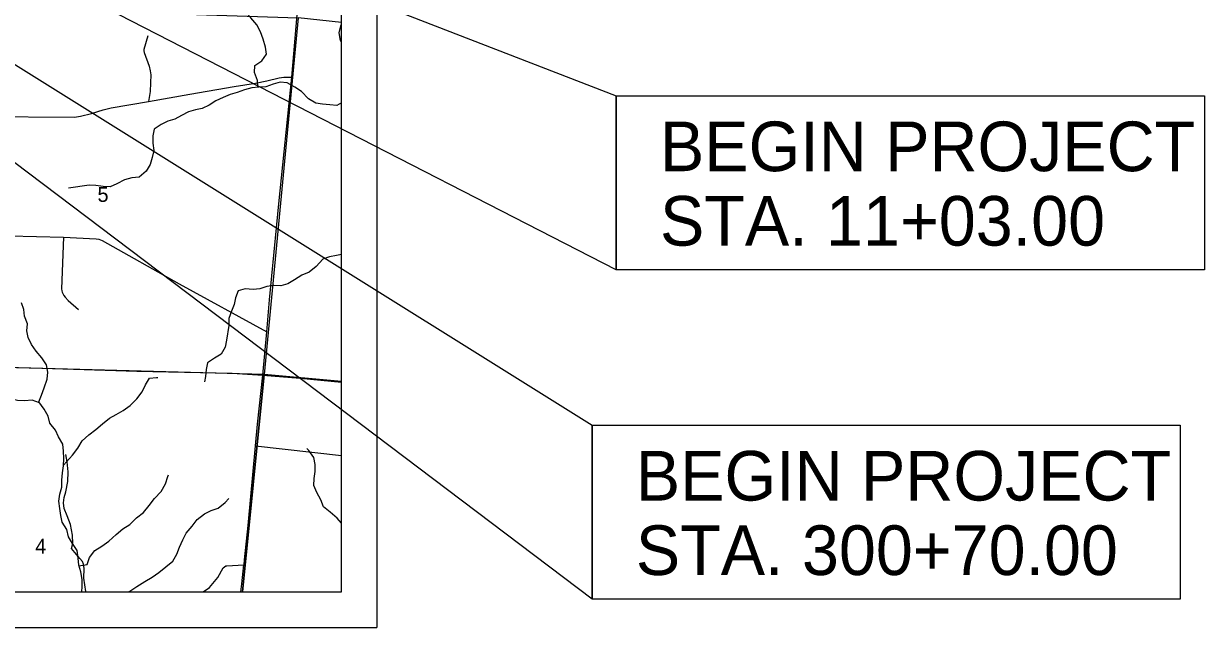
# Model space of a CAD drawing. Extents: x 0 to 34, y -3.9 to 26.2.
# Drawn here: x 8.005 to 11.332, y 14 to 15.703 of the extents above; entities that cross this region are included whole.
import ezdxf

# ---------------------------------------------------------------- set-up
doc = ezdxf.new("R2010")
doc.units = 0
for name, color, linetype in [('GM_X_City_Street', 7, 'Continuous'), ('GM_X_Interchange_Ramps', 7, 'Continuous'), ('GM_X_Interstate_Route', 7, 'Continuous'), ('GM_X_Minor_River', 7, 'Continuous'), ('GM_X_Section', 7, 'Continuous'), ('GM_X_Section_Text', 7, 'Continuous'), ('GM_X_State_Shield', 7, 'Continuous'), ('SH_Data', 7, 'Continuous'), ('SH_Text', 7, 'Continuous')]:
    doc.layers.add(name, color=color, linetype=linetype)

msp = doc.modelspace()

# ---------------------------------------------------------------- linework, layer by layer
at = {"layer": 'GM_X_City_Street'}
msp.add_line((8.6583, 14.512), (8.9, 14.4851), dxfattribs=at)
for points in [[(8.617, 14.1), (8.6198, 14.1232), (8.6255, 14.1764), (8.6256, 14.1778), (8.627, 14.1907), (8.6376, 14.2877), (8.6583, 14.512), (8.664, 14.573), (8.6788, 14.7113), (8.6895, 14.8334), (8.6975, 14.9238), (8.7234, 15.1949), (8.7607, 15.5523), (8.7755, 15.7284), (8.7818, 15.7929), (8.8003, 15.9821), (8.8096, 16.1005)], [(8.3546, 15.6685), (8.3434, 15.6304), (8.3432, 15.6283), (8.3433, 15.6263), (8.3446, 15.6221), (8.358, 15.5833), (8.3609, 15.5698), (8.3627, 15.5588), (8.3624, 15.536), (8.361, 15.5118), (8.356, 15.4837)], [(7.887, 15.4412), (8.1481, 15.4396), (8.1652, 15.4422), (8.1958, 15.4494), (8.2287, 15.4599), (8.2516, 15.4654), (8.356, 15.4837), (8.4725, 15.504), (8.5983, 15.5254), (8.6578, 15.5349), (8.6898, 15.5416), (8.7246, 15.5506), (8.738, 15.5525), (8.7607, 15.5523)], [(7.9645, 15.1041), (8.1174, 15.1004), (8.2093, 15.0964), (8.2169, 15.095), (8.2209, 15.0935), (8.2262, 15.0911), (8.4427, 14.9693), (8.6895, 14.8334)], [(8.1174, 15.1004), (8.1116, 14.9553), (8.1122, 14.9494), (8.1132, 14.9455), (8.1146, 14.9423), (8.1178, 14.9365), (8.1212, 14.9319), (8.1304, 14.9218), (8.1594, 14.897)], [(7.8755, 14.7356), (8.0556, 14.7316), (8.3232, 14.723), (8.592, 14.7171), (8.6788, 14.7113), (8.784, 14.7033), (8.9, 14.6919)], [(8.1801, 14.1), (8.1798, 14.1011), (8.174, 14.1385), (8.1751, 14.1658), (8.1732, 14.1788), (8.1704, 14.1861), (8.163, 14.1943), (8.1395, 14.223), (8.1429, 14.2366), (8.142, 14.2606), (8.1368, 14.2904), (8.1272, 14.3146), (8.119, 14.3354), (8.1171, 14.3514), (8.1187, 14.3666), (8.1237, 14.382), (8.1287, 14.4119), (8.1302, 14.4393), (8.1271, 14.4671), (8.1231, 14.4881)], [(8.5106, 14.1), (8.528, 14.1127), (8.5519, 14.141), (8.5671, 14.1676), (8.571, 14.1713), (8.5741, 14.1733), (8.5772, 14.1741), (8.6255, 14.1764)]]:
    msp.add_lwpolyline(points, dxfattribs=at)
at = {"layer": 'GM_X_Interchange_Ramps'}
msp.add_lwpolyline([(7.395, 14.1), (8.9, 14.1), (8.9, 20.3498)], dxfattribs=at)
at = {"layer": 'GM_X_Interstate_Route'}
msp.add_lwpolyline([(2.5468, 14.1), (8.9, 14.1), (8.9, 16.7226), (8.8708, 16.7253), (8.3218, 16.7826), (8.2541, 16.7887), (8.1936, 16.7941), (8.1769, 16.7957), (7.8848, 16.8273)], dxfattribs=at)
at = {"layer": 'GM_X_Minor_River'}
for points in [[(8.665, 15.5234), (8.6632, 15.543), (8.6552, 15.565), (8.6563, 15.5848), (8.6758, 15.5981), (8.6891, 15.6171), (8.6861, 15.6365), (8.68, 15.6594), (8.6716, 15.6799), (8.6613, 15.7001), (8.6449, 15.7199), (8.6274, 15.7393), (8.6171, 15.7587), (8.5961, 15.7781), (8.5946, 15.7994), (8.5988, 15.8184), (8.6041, 15.8393), (8.6087, 15.861), (8.6113, 15.877)], [(8.9, 15.6502), (8.8976, 15.6556), (8.8941, 15.6769), (8.8983, 15.697), (8.9, 15.7)], [(8.9, 15.4796), (8.8869, 15.4726), (8.8675, 15.4745), (8.8469, 15.4756), (8.8278, 15.479), (8.8076, 15.4912), (8.7874, 15.5114), (8.7684, 15.5236), (8.747, 15.5357), (8.7276, 15.538), (8.7078, 15.5327), (8.6868, 15.5247), (8.6674, 15.5236), (8.648, 15.522), (8.6274, 15.5163), (8.606, 15.5091), (8.5862, 15.503), (8.5668, 15.495), (8.5466, 15.4851), (8.5271, 15.4733), (8.5081, 15.4635), (8.4886, 15.4596), (8.4692, 15.4547), (8.4494, 15.444), (8.4303, 15.4338), (8.4113, 15.4277), (8.3918, 15.4182), (8.3724, 15.4056), (8.3686, 15.3866), (8.369, 15.3661), (8.3713, 15.3448), (8.3671, 15.3257), (8.361, 15.3056), (8.3499, 15.2865), (8.3297, 15.2702), (8.3091, 15.2683), (8.2886, 15.2622), (8.2676, 15.2508), (8.2482, 15.2428), (8.2283, 15.2439), (8.2082, 15.2466), (8.1891, 15.247), (8.1697, 15.2447), (8.1506, 15.242), (8.1308, 15.2394)], [(8.9, 15.0517), (8.8858, 15.0495), (8.8663, 15.0449), (8.8473, 15.0385), (8.8286, 15.0179), (8.8088, 15.0019), (8.7882, 14.9932), (8.7676, 14.9802), (8.7486, 14.9696), (8.7291, 14.9635), (8.7097, 14.9643), (8.6895, 14.9616), (8.6704, 14.9555), (8.651, 14.9536), (8.6289, 14.9551), (8.6091, 14.9494), (8.6018, 14.93), (8.5976, 14.9106), (8.59, 14.8916), (8.5828, 14.8718), (8.5824, 14.8513), (8.5763, 14.8102), (8.5725, 14.7904), (8.5614, 14.7706), (8.5424, 14.7599), (8.5229, 14.7466), (8.5191, 14.7276), (8.5168, 14.7078), (8.5138, 14.693)], [(8.1683, 14.1), (8.1692, 14.1157), (8.1692, 14.1348), (8.1658, 14.1565), (8.1597, 14.1759), (8.1578, 14.1956), (8.1551, 14.2166), (8.1422, 14.2367), (8.1307, 14.2558), (8.1262, 14.2759), (8.1136, 14.2969), (8.1094, 14.3159), (8.1067, 14.3357), (8.1041, 14.3562), (8.1064, 14.376), (8.1121, 14.3958), (8.1125, 14.4156), (8.1144, 14.4358), (8.1167, 14.4555), (8.1178, 14.4765), (8.117, 14.4974), (8.1148, 14.5168), (8.1033, 14.5374), (8.0946, 14.5564), (8.0782, 14.5762), (8.0736, 14.5963), (8.0625, 14.6154), (8.0477, 14.6359), (8.0545, 14.6553), (8.0629, 14.6762), (8.0709, 14.6998), (8.0728, 14.7196), (8.0687, 14.7409), (8.0557, 14.76), (8.0397, 14.7794), (8.0271, 14.7984), (8.0172, 14.8178), (8.0138, 14.8368), (8.0153, 14.8562), (8.0073, 14.8775), (8.005, 14.8966), (7.9985, 14.9156)], [(8.1167, 14.4572), (8.1258, 14.4666), (8.1422, 14.486), (8.1571, 14.5054), (8.1696, 14.5259), (8.1887, 14.5431), (8.2078, 14.5583), (8.2272, 14.5746), (8.2462, 14.5906), (8.2657, 14.6009), (8.2855, 14.6119), (8.3046, 14.626), (8.3236, 14.645), (8.3389, 14.6648), (8.3484, 14.6838), (8.3591, 14.7029), (8.3789, 14.7048), (8.3831, 14.7048)], [(8.0494, 14.6336), (8.029, 14.6409), (8.0073, 14.6393), (7.9871, 14.6401), (7.9673, 14.6447), (7.9471, 14.6481), (7.9276, 14.6447), (7.9074, 14.6355), (7.8876, 14.6237), (7.8689, 14.6043), (7.8476, 14.591), (7.827, 14.5895), (7.8072, 14.5887), (7.7881, 14.5925), (7.7721, 14.6127), (7.7569, 14.6321), (7.7375, 14.6409), (7.7146, 14.6405), (7.7009, 14.6359)], [(8.9, 14.2943), (8.8877, 14.3079), (8.8686, 14.3254), (8.8492, 14.3399), (8.8419, 14.3596), (8.8309, 14.3806), (8.8225, 14.4007), (8.8236, 14.4205), (8.8259, 14.4399), (8.8263, 14.4597), (8.8221, 14.4791), (8.808, 14.4989), (8.8023, 14.5046)], [(8.1605, 14.1733), (8.1837, 14.177), (8.1906, 14.1968), (8.2051, 14.217), (8.2249, 14.2288), (8.2443, 14.2436), (8.2653, 14.2619), (8.2843, 14.2782), (8.3034, 14.2904), (8.3228, 14.3087), (8.3423, 14.3243), (8.3587, 14.344), (8.3731, 14.3638), (8.3918, 14.3832), (8.4048, 14.4049), (8.4105, 14.4255), (8.4124, 14.4308)], [(8.2999, 14.1), (8.3038, 14.1024), (8.3236, 14.1157), (8.3457, 14.1294), (8.3667, 14.1416), (8.3857, 14.1549), (8.4052, 14.1709), (8.4254, 14.1869), (8.436, 14.2067), (8.4436, 14.2261), (8.4536, 14.2466), (8.4627, 14.2657), (8.4791, 14.2854), (8.4936, 14.3045), (8.5142, 14.3208), (8.5332, 14.33), (8.5523, 14.3361), (8.5725, 14.3528), (8.5824, 14.3635)]]:
    msp.add_lwpolyline(points, dxfattribs=at)
at = {"layer": 'GM_X_Section'}
msp.add_lwpolyline([(8.7783, 15.7191), (8.6823, 14.7132), (7.6773, 14.7406), (7.7738, 15.7526)], close=True, dxfattribs=at)
at = {"layer": 'GM_X_State_Shield'}
for points in [[(8.9, 14.6934), (8.9, 15.7064), (8.7783, 15.7191), (8.6823, 14.7132)], [(7.6139, 14.1), (8.6213, 14.1), (8.6823, 14.7132), (7.6773, 14.7406)], [(8.6213, 14.1), (8.9, 14.1), (8.9, 14.6934), (8.6823, 14.7132)]]:
    msp.add_lwpolyline(points, close=True, dxfattribs=at)
at = {"layer": 'SH_Data'}
for p in [(9, 21), (2, 14)]:
    msp.add_line(p, (9, 14), dxfattribs=at)
at = {"layer": 'SH_Text'}
for points in [[(9.6746, 15.4992), (9.6746, 15.0088), (5.7921, 17.0032)], [(9.6066, 14.5701), (9.6066, 14.0797), (5.8602, 16.9149)], [(9.6746, 15.4992), (11.3317, 15.4992), (11.3317, 15.0088), (9.6746, 15.0088)], [(9.6066, 14.5701), (11.2637, 14.5701), (11.2637, 14.0797), (9.6066, 14.0797)]]:
    msp.add_lwpolyline(points, close=True, dxfattribs=at)

# ---------------------------------------------------------------- texts
at = {"layer": 'GM_X_Section_Text'}
for s, p in [('5', (8.2127, 15.2002)), ('4', (8.0373, 14.2083))]:
    msp.add_text(s, height=0.0419, rotation=0, dxfattribs=at).set_placement(p)
at = {"layer": 'SH_Text'}
for s, p in [('BEGIN PROJECT', (9.7977, 15.2869)), ('STA. 11+03.00', (9.7977, 15.0769)), ('BEGIN PROJECT', (9.7297, 14.3578)), ('STA. 300+70.00', (9.7297, 14.1478))]:
    msp.add_text(s, height=0.14, dxfattribs=at).set_placement(p)

doc.saveas('drawing.dxf')
